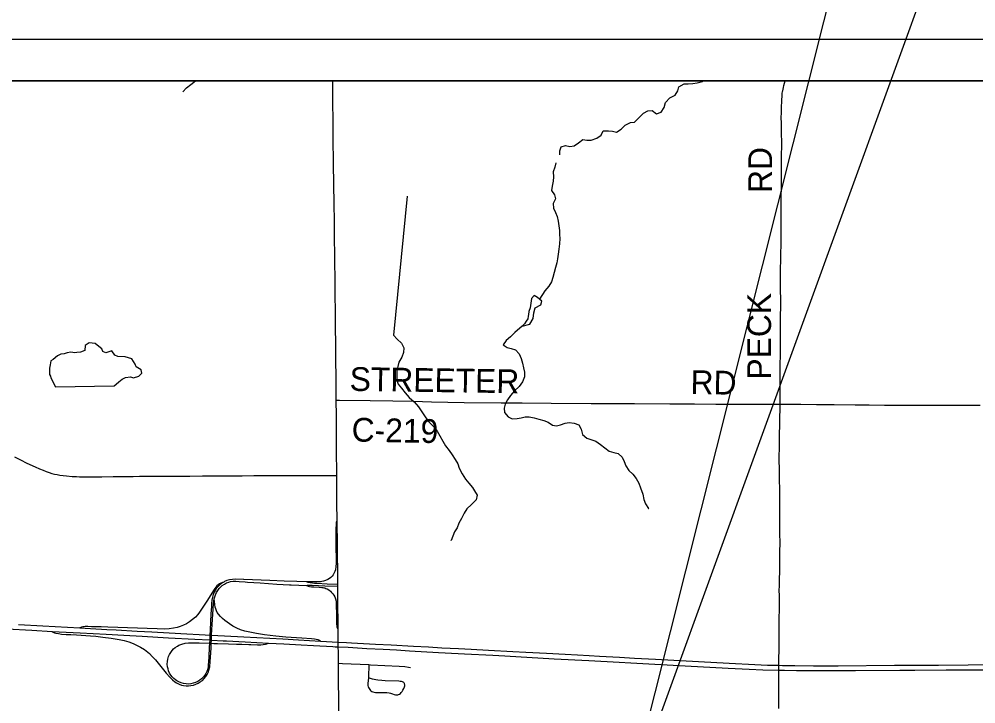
# Model space of a CAD drawing. Extents: x 0 to 34, y 0 to 22.
# Drawn here: x 25.975 to 28.262, y 18.436 to 20.071 of the extents above; entities that cross this region are included whole.
import ezdxf

# ---------------------------------------------------------------- set-up
doc = ezdxf.new("R2010")
doc.units = 0
for name, color, linetype in [('GM_X_Corporation', 7, 'Continuous'), ('GM_X_County_Road', 7, 'Continuous'), ('GM_X_County_Road_Text', 7, 'Continuous'), ('GM_X_Interchange_Ramps', 7, 'Continuous'), ('GM_X_Interstate_Route', 7, 'Continuous'), ('GM_X_Minor_Lake', 7, 'Continuous'), ('GM_X_Minor_River', 7, 'Continuous'), ('GM_X_State_Route', 7, 'Continuous'), ('GM_X_Township_Road', 7, 'Continuous'), ('SH_Data', 7, 'Continuous'), ('SH_Text', 7, 'Continuous')]:
    doc.layers.add(name, color=color, linetype=linetype)

msp = doc.modelspace()

# ---------------------------------------------------------------- linework, layer by layer
at = {"layer": 'GM_X_Corporation'}
msp.add_lwpolyline([(28.775, 16.6777), (28.7553, 18.174), (28.7532, 18.52), (28.7531, 18.5321), (28.758, 19.3951), (28.7506, 19.9239), (23.4438, 19.9239), (23.4438, 15.6034)], dxfattribs=at)
at = {"layer": 'GM_X_County_Road'}
for points in [[(27.7938, 19.1518), (27.7939, 19.1583), (27.794, 19.1918), (27.7944, 19.2353), (27.795, 19.2801), (27.7946, 19.3018), (27.7949, 19.3335), (27.7952, 19.3602), (27.7954, 19.3863), (27.7955, 19.4044), (27.7952, 19.4228), (27.7949, 19.4389), (27.7953, 19.4712), (27.7957, 19.4998), (27.796, 19.5171), (27.7963, 19.5271), (27.7963, 19.532), (27.7966, 19.549), (27.7966, 19.5841), (27.7966, 19.594), (27.7967, 19.6082), (27.7968, 19.6295), (27.7968, 19.6467), (27.7971, 19.6701), (27.7971, 19.6873), (27.7973, 19.7172), (27.7976, 19.7455), (27.7978, 19.7694), (27.7971, 19.8065), (27.7972, 19.8232), (27.7968, 19.8369), (27.797, 19.8473), (27.7973, 19.8597), (27.7981, 19.8773), (27.7987, 19.8887), (27.7991, 19.8939), (27.8, 19.8987), (27.8002, 19.9004), (27.802, 19.9082), (27.8031, 19.913), (27.806, 19.9239)], [(26.7331, 19.161), (26.7411, 19.1609), (26.8144, 19.1601), (26.8683, 19.1597), (26.9175, 19.159), (26.9608, 19.1573), (27.0385, 19.156), (27.1277, 19.1552), (27.1773, 19.1552), (27.2465, 19.1543), (27.3425, 19.1536), (27.3897, 19.1534), (27.4462, 19.1534), (27.5301, 19.1528), (27.5897, 19.1525), (27.6407, 19.152), (27.7333, 19.1516), (27.7938, 19.1518)], [(27.7907, 18.4249), (27.7908, 18.4405), (27.791, 18.4585), (27.7909, 18.4665), (27.7908, 18.4777), (27.7908, 18.4821), (27.791, 18.5094), (27.791, 18.5161), (27.7911, 18.5231), (27.7911, 18.5278), (27.7912, 18.5448), (27.7915, 18.5635), (27.7915, 18.5796), (27.7917, 18.5871), (27.792, 18.6057), (27.792, 18.6324), (27.7923, 18.6691), (27.7923, 18.6827), (27.7922, 18.69), (27.7922, 18.6919), (27.7923, 18.6961), (27.7921, 18.7047), (27.7923, 18.719), (27.7927, 18.7295), (27.7929, 18.7388), (27.793, 18.7462), (27.7931, 18.7491), (27.7932, 18.7633), (27.7933, 18.7801), (27.7937, 18.8), (27.7938, 18.8192), (27.7934, 18.8434), (27.793, 18.8837), (27.7932, 18.9057), (27.7931, 18.9325), (27.7924, 18.9867), (27.7921, 19.0273), (27.7925, 19.0463), (27.7929, 19.0737), (27.7933, 19.1079), (27.7938, 19.1518)], [(27.7938, 19.1518), (27.8017, 19.1517), (27.8434, 19.1514), (27.8808, 19.151), (27.9231, 19.1506), (27.9731, 19.1502), (28.0066, 19.1497), (28.0434, 19.1494), (28.0659, 19.1493), (28.1051, 19.1494), (28.1567, 19.1491), (28.1815, 19.1492), (28.2132, 19.1491), (28.2724, 19.149)]]:
    msp.add_lwpolyline(points, dxfattribs=at)
at = {"layer": 'GM_X_Interchange_Ramps'}
msp.add_line((26.6257, 18.7198), (26.6619, 18.7183), dxfattribs=at)
for points in [[(26.7351, 18.8718), (26.7345, 18.8715), (26.734, 18.871), (26.7333, 18.8696), (26.7331, 18.8684), (26.7328, 18.8634), (26.7324, 18.8556), (26.7321, 18.8308), (26.7324, 18.8119), (26.7326, 18.7804), (26.7327, 18.7706), (26.7325, 18.7644), (26.7323, 18.7616), (26.7317, 18.7581), (26.7311, 18.7555), (26.7298, 18.7516), (26.7276, 18.7471), (26.7258, 18.7441), (26.7235, 18.741), (26.7204, 18.7378), (26.7171, 18.7352), (26.7128, 18.7324), (26.7075, 18.73), (26.7028, 18.7284), (26.6991, 18.7278), (26.6957, 18.7275), (26.6893, 18.7275), (26.6834, 18.7275), (26.6754, 18.7273), (26.6692, 18.7272), (26.6623, 18.7269)], [(26.4648, 18.7268), (26.4616, 18.7256), (26.4577, 18.7242), (26.4541, 18.7226), (26.4509, 18.7202), (26.4478, 18.7174), (26.4451, 18.7143), (26.4411, 18.7087), (26.4238, 18.6814), (26.4158, 18.6688), (26.4065, 18.6549), (26.4024, 18.6495), (26.3966, 18.6431), (26.3896, 18.6369), (26.3826, 18.6317), (26.3752, 18.6272), (26.3679, 18.6237), (26.3598, 18.6205), (26.3527, 18.6183), (26.3442, 18.6164), (26.3338, 18.6151), (26.322, 18.6145), (26.3052, 18.6146), (26.1871, 18.6189), (26.1713, 18.6193), (26.1483, 18.6199), (26.1397, 18.6201), (26.1332, 18.6202), (26.1298, 18.62), (26.1277, 18.6196), (26.1247, 18.619), (26.1226, 18.6183), (26.1201, 18.6174)], [(26.4648, 18.7268), (26.46, 18.7237), (26.4549, 18.7198), (26.4506, 18.7158), (26.4472, 18.7117), (26.4443, 18.7076), (26.4416, 18.7025), (26.4392, 18.6972), (26.4373, 18.6908), (26.4361, 18.6835), (26.4353, 18.6752), (26.4348, 18.668), (26.4338, 18.6504), (26.4319, 18.6121), (26.4313, 18.6001), (26.4307, 18.5883), (26.4303, 18.5804), (26.4298, 18.5705), (26.4286, 18.5486), (26.4278, 18.5352), (26.4274, 18.5295), (26.4268, 18.5242), (26.4262, 18.5207), (26.4251, 18.5168), (26.4237, 18.5126), (26.4217, 18.5086), (26.4188, 18.504), (26.4159, 18.5002), (26.4114, 18.4955), (26.4069, 18.4922), (26.4022, 18.4891), (26.3971, 18.4866), (26.3916, 18.4848), (26.3855, 18.4834), (26.3794, 18.4829), (26.3741, 18.4832), (26.3678, 18.4842), (26.3624, 18.4857), (26.3572, 18.4879), (26.3525, 18.4906), (26.3486, 18.4931), (26.3448, 18.4964), (26.3409, 18.5004), (26.3377, 18.5044), (26.335, 18.5089), (26.3326, 18.5144), (26.3311, 18.5195), (26.3299, 18.5243), (26.3294, 18.5305), (26.3299, 18.5372), (26.3309, 18.5427), (26.3326, 18.5487), (26.3345, 18.5533), (26.3376, 18.5587), (26.3409, 18.5632), (26.3443, 18.5668), (26.3485, 18.5705), (26.3537, 18.5739), (26.357, 18.5756), (26.3639, 18.5785), (26.3717, 18.5804), (26.3798, 18.5814), (26.3891, 18.5817), (26.4058, 18.5812), (26.4299, 18.5804)], [(26.4416, 18.6865), (26.4447, 18.6963), (26.4471, 18.7019), (26.4498, 18.7067), (26.453, 18.7111), (26.4572, 18.7156), (26.4609, 18.7187), (26.466, 18.722), (26.471, 18.7245), (26.4766, 18.7265), (26.4808, 18.7276), (26.4868, 18.7285), (26.4934, 18.7286), (26.5015, 18.7279), (26.5154, 18.727)], [(26.5112, 18.7328), (26.4918, 18.7332), (26.485, 18.7328), (26.4778, 18.7316), (26.4719, 18.7302), (26.4664, 18.7277), (26.4648, 18.7268)], [(26.6623, 18.7269), (26.6389, 18.7278), (26.609, 18.7288), (26.5741, 18.7301), (26.5122, 18.7328), (26.5112, 18.7328)], [(26.5154, 18.727), (26.5213, 18.7266), (26.5515, 18.7247), (26.5911, 18.7219), (26.6216, 18.72), (26.6257, 18.7198)], [(26.737, 18.7211), (26.7112, 18.7218), (26.6871, 18.723), (26.6809, 18.7234), (26.6768, 18.7238), (26.671, 18.7247), (26.666, 18.7257), (26.6623, 18.7269)], [(26.6619, 18.7183), (26.6643, 18.7189), (26.667, 18.7192), (26.671, 18.7193), (26.6758, 18.7192), (26.7057, 18.718), (26.7371, 18.7168)], [(26.6619, 18.7183), (26.6657, 18.717), (26.6695, 18.7161), (26.674, 18.7156), (26.6796, 18.7153), (26.6927, 18.7144), (26.6985, 18.714), (26.7011, 18.7137), (26.7036, 18.7132), (26.7058, 18.7126), (26.7084, 18.7116), (26.7111, 18.7105), (26.7154, 18.708), (26.7193, 18.7049), (26.7222, 18.7021), (26.7254, 18.6983), (26.7276, 18.695), (26.7298, 18.691), (26.7315, 18.6868), (26.7326, 18.6814), (26.7331, 18.6764), (26.7333, 18.6705), (26.7334, 18.6503), (26.7335, 18.6428), (26.7338, 18.6282), (26.7345, 18.6191), (26.735, 18.6173), (26.7359, 18.6155), (26.7367, 18.6147), (26.7377, 18.6141)], [(26.0545, 18.6088), (26.0566, 18.6071), (26.0595, 18.6056), (26.0629, 18.6046), (26.0695, 18.6035), (26.0767, 18.6025), (26.0878, 18.6017), (26.0989, 18.601), (26.112, 18.6004), (26.1238, 18.5998), (26.1349, 18.5991), (26.1461, 18.5981), (26.1585, 18.5972), (26.1752, 18.5954), (26.1955, 18.5925), (26.2145, 18.5892), (26.226, 18.5867), (26.2374, 18.5836), (26.2479, 18.5797), (26.2575, 18.5753), (26.2657, 18.5708), (26.2746, 18.5652), (26.2826, 18.5592), (26.2868, 18.5556), (26.2935, 18.5491), (26.301, 18.5408), (26.327, 18.509), (26.3356, 18.4992), (26.3418, 18.4931), (26.3477, 18.4884), (26.3512, 18.486), (26.3579, 18.4825), (26.3637, 18.4804), (26.3679, 18.4794), (26.3741, 18.4787), (26.3797, 18.4786), (26.3859, 18.4792), (26.3919, 18.4805), (26.3979, 18.4825), (26.403, 18.4848), (26.4083, 18.488), (26.4132, 18.4918), (26.4176, 18.4961), (26.4216, 18.501), (26.4249, 18.5062), (26.4275, 18.5118), (26.429, 18.5159), (26.431, 18.5244), (26.4322, 18.5368), (26.4329, 18.5473), (26.4339, 18.5685), (26.4345, 18.5803), (26.4348, 18.5881), (26.4352, 18.5946), (26.4354, 18.5999), (26.4367, 18.625), (26.4387, 18.6622), (26.44, 18.6752), (26.4406, 18.6807), (26.4416, 18.6865)], [(26.6953, 18.5857), (26.6933, 18.5867), (26.6899, 18.5884), (26.6855, 18.5897), (26.6815, 18.5904), (26.6739, 18.5911), (26.651, 18.5927), (26.6126, 18.5951), (26.5884, 18.5972), (26.5749, 18.5987), (26.5619, 18.6005), (26.5423, 18.6037), (26.5265, 18.6067), (26.5144, 18.6097), (26.5044, 18.6129), (26.4952, 18.6168), (26.4864, 18.6214), (26.478, 18.6267), (26.4671, 18.6349), (26.4614, 18.6398), (26.4565, 18.6445), (26.452, 18.6496), (26.4489, 18.6542), (26.4467, 18.6582), (26.4451, 18.6627), (26.444, 18.6664), (26.4429, 18.6732), (26.4416, 18.6865)], [(26.431, 18.5804), (26.4345, 18.5803), (26.4409, 18.5801), (26.4495, 18.5798), (26.4756, 18.5789), (26.4944, 18.5783), (26.5078, 18.578), (26.5245, 18.5775), (26.5288, 18.5773), (26.5447, 18.5769), (26.5526, 18.5769), (26.5587, 18.5773), (26.5642, 18.578), (26.5673, 18.5791), (26.5713, 18.5808)]]:
    msp.add_lwpolyline(points, dxfattribs=at)
at = {"layer": 'GM_X_Interstate_Route'}
for points in [[(25.9456, 18.6153), (26.0053, 18.6114), (26.0545, 18.6088), (26.1213, 18.6055), (26.1835, 18.602), (26.2253, 18.5996), (26.2697, 18.5971), (26.3326, 18.5938), (26.3953, 18.5901), (26.4307, 18.5883), (26.4348, 18.5881), (26.4626, 18.5866)], [(25.9739, 18.6251), (26.0317, 18.6221), (26.1201, 18.6174)], [(26.1201, 18.6174), (26.1461, 18.6159), (26.185, 18.6137), (26.2069, 18.6125), (26.2576, 18.6097), (26.2924, 18.6079), (26.3618, 18.604), (26.4196, 18.6007), (26.4313, 18.6001), (26.4354, 18.5999), (26.5121, 18.5958), (26.6055, 18.5907), (26.6428, 18.5886), (26.6953, 18.5857), (26.738, 18.5833), (26.7577, 18.5822), (26.7694, 18.5816), (26.8273, 18.5785), (26.8646, 18.5766), (26.9181, 18.5736), (26.954, 18.5716), (26.9854, 18.5699), (27.0255, 18.5677), (27.0559, 18.566), (27.0968, 18.564), (27.1555, 18.5608), (27.1863, 18.5591), (27.2354, 18.5565), (27.2804, 18.5541), (27.31, 18.5526), (27.3379, 18.5509), (27.3626, 18.5495), (27.4104, 18.5469), (27.4457, 18.5451), (27.4962, 18.5422), (27.5991, 18.5366), (27.6719, 18.5328), (27.7332, 18.5298), (27.7639, 18.5285), (27.7837, 18.528), (27.7911, 18.5278), (27.8, 18.5277), (27.8291, 18.5271), (27.8736, 18.5267), (27.9327, 18.5268), (28.0677, 18.5278), (28.1722, 18.5285), (28.3143, 18.5295)], [(26.4626, 18.5866), (26.4705, 18.5862), (26.5152, 18.5838), (26.5713, 18.5808), (26.608, 18.5787), (26.649, 18.5764), (26.6792, 18.5749), (26.7247, 18.5725), (26.7309, 18.5722)], [(26.7309, 18.5722), (26.7381, 18.5719), (26.7616, 18.5708), (26.8064, 18.5683), (26.8454, 18.5662), (26.877, 18.5644), (26.9084, 18.5626), (26.9772, 18.5587), (26.9934, 18.5578), (27.04, 18.5553), (27.1075, 18.5517), (27.1361, 18.5502), (27.254, 18.5435), (27.3367, 18.5392), (27.4094, 18.5352), (27.437, 18.5337), (27.5674, 18.5267), (27.6701, 18.5211), (27.7199, 18.5184), (27.7528, 18.517), (27.791, 18.5161), (27.8044, 18.5158), (27.8331, 18.5155), (27.8682, 18.5151), (27.899, 18.5152), (27.9434, 18.5153), (27.9739, 18.5154), (28.0805, 18.516), (28.1156, 18.5162), (28.1907, 18.5169), (28.2201, 18.5172), (28.3081, 18.5173)]]:
    msp.add_lwpolyline(points, dxfattribs=at)
at = {"layer": 'GM_X_Minor_Lake'}
for p, q in [((27.1994, 19.3985), (27.1965, 19.3818)), ((26.051, 19.2144), (26.0621, 19.1928))]:
    msp.add_line(p, q, dxfattribs=at)
for points in [[(27.1965, 19.3818), (27.1935, 19.3734), (27.1928, 19.3658), (27.192, 19.362), (27.1909, 19.3555), (27.1871, 19.3502), (27.1834, 19.3433), (27.1779, 19.3382), (27.1959, 19.3426), (27.2038, 19.3567), (27.2053, 19.3697), (27.2086, 19.3818), (27.2219, 19.3888), (27.2249, 19.3979), (27.2142, 19.4062), (27.2062, 19.4111), (27.2002, 19.4039), (27.1994, 19.3985)], [(26.0621, 19.1928), (26.2026, 19.1951), (26.2075, 19.1996), (26.2139, 19.205), (26.2215, 19.2115), (26.2294, 19.2157), (26.2416, 19.2173), (26.2484, 19.2147), (26.2617, 19.2189), (26.2685, 19.2254), (26.2669, 19.2334), (26.2547, 19.2406), (26.2524, 19.2474), (26.2444, 19.2599), (26.2288, 19.2644), (26.2114, 19.2658), (26.2038, 19.2684), (26.1969, 19.279), (26.1821, 19.274), (26.1752, 19.2774), (26.1733, 19.2842), (26.1619, 19.2929), (26.1569, 19.2967), (26.1425, 19.2985), (26.1334, 19.292), (26.1327, 19.2802), (26.1221, 19.2756), (26.1134, 19.2752), (26.1085, 19.2744), (26.099, 19.2759), (26.0899, 19.2743), (26.0827, 19.272), (26.0751, 19.2712), (26.0671, 19.267), (26.0565, 19.2586), (26.0512, 19.2551), (26.0498, 19.246), (26.0479, 19.2376), (26.0476, 19.2289), (26.048, 19.2224), (26.0499, 19.2182), (26.051, 19.2144)]]:
    msp.add_lwpolyline(points, dxfattribs=at)
at = {"layer": 'GM_X_Minor_River'}
for points in [[(26.3667, 19.8976), (26.3754, 19.9071), (26.386, 19.9152), (26.3967, 19.9239)], [(27.2677, 19.7471), (27.2676, 19.7569), (27.2706, 19.7665), (27.2812, 19.7699), (27.2911, 19.7669), (27.3017, 19.7689), (27.3123, 19.7758), (27.3222, 19.7842), (27.3317, 19.7824), (27.3427, 19.782), (27.3559, 19.787), (27.3665, 19.7947), (27.3714, 19.8046), (27.3836, 19.805), (27.3934, 19.8036), (27.4029, 19.8017), (27.4139, 19.809), (27.4237, 19.8182), (27.4362, 19.8247), (27.4461, 19.8255), (27.4567, 19.8358), (27.4676, 19.8465), (27.4778, 19.8527), (27.4885, 19.8535), (27.4984, 19.8452), (27.5097, 19.849), (27.5169, 19.8601), (27.5203, 19.8726), (27.5308, 19.8837), (27.5433, 19.8899), (27.5497, 19.9005), (27.552, 19.9101), (27.5645, 19.9173), (27.574, 19.917), (27.585, 19.9174), (27.5956, 19.9194), (27.6085, 19.9229), (27.6101, 19.9239)], [(27.2583, 19.728), (27.2557, 19.7177), (27.2512, 19.7071), (27.2524, 19.6945), (27.2516, 19.6843), (27.2494, 19.6728), (27.2476, 19.6622), (27.2548, 19.6516), (27.2572, 19.6421), (27.2515, 19.6314), (27.2527, 19.6196), (27.2573, 19.6094), (27.2611, 19.5999), (27.2638, 19.5885), (27.265, 19.5775), (27.2666, 19.5665), (27.2667, 19.5566), (27.2675, 19.5471), (27.2668, 19.5346), (27.2653, 19.5216), (27.2634, 19.5098), (27.2616, 19.4992), (27.2601, 19.4893), (27.2575, 19.4779), (27.2542, 19.4661), (27.2508, 19.4539), (27.2474, 19.4436), (27.241, 19.4337), (27.2316, 19.4223), (27.219, 19.4024)], [(26.903, 19.6483), (26.87, 19.3167), (26.8788, 19.3068), (26.8891, 19.2974), (26.8944, 19.286), (26.8941, 19.275), (26.8903, 19.2643), (26.8824, 19.2521), (26.8806, 19.2418), (26.878, 19.2319), (26.878, 19.222), (26.8777, 19.2099), (26.8812, 19.1996), (26.8892, 19.1898), (26.8979, 19.1784), (26.9075, 19.1678), (26.9197, 19.1573), (26.93, 19.1451), (26.9453, 19.1217), (26.9544, 19.1092), (26.967, 19.0971), (26.9747, 19.0872), (26.9808, 19.0758), (26.988, 19.0633), (26.9945, 19.052), (27.0029, 19.0406), (27.0106, 19.0308), (27.0175, 19.0198), (27.0236, 19.0088), (27.0271, 18.9985), (27.0343, 18.9849), (27.0424, 18.9728), (27.0504, 18.9629), (27.0588, 18.9523), (27.0637, 18.9447)], [(27.1779, 19.3382), (27.1603, 19.3227), (27.1493, 19.3127), (27.1395, 19.3036), (27.132, 19.2933), (27.1419, 19.2872), (27.1514, 19.2846), (27.1616, 19.2816), (27.1704, 19.2718), (27.1754, 19.2608), (27.1785, 19.2498), (27.1808, 19.2388), (27.1828, 19.2285), (27.1828, 19.2167), (27.1787, 19.2053), (27.17, 19.1939), (27.1594, 19.1832), (27.15, 19.1725), (27.1424, 19.1622), (27.1368, 19.1515), (27.1346, 19.142), (27.1354, 19.1317), (27.1438, 19.1215), (27.154, 19.117), (27.1658, 19.1178), (27.1753, 19.1194), (27.1848, 19.1213), (27.1946, 19.121), (27.2064, 19.1188), (27.217, 19.1162), (27.2292, 19.1128), (27.2395, 19.1087), (27.2498, 19.1012), (27.2596, 19.1001), (27.2695, 19.1024), (27.2805, 19.1066), (27.29, 19.1078), (27.3017, 19.106), (27.3127, 19.1019), (27.3189, 19.0916), (27.3216, 19.0795), (27.3322, 19.0704), (27.3539, 19.0633), (27.365, 19.0554), (27.3752, 19.0474), (27.3855, 19.0391), (27.3969, 19.0365), (27.4068, 19.0339), (27.4163, 19.0248), (27.4213, 19.0146), (27.4255, 19.0044), (27.4324, 18.993), (27.4423, 18.9847), (27.4503, 18.9737), (27.4565, 18.9631), (27.4603, 18.9517)], [(27.0637, 18.9447), (27.0701, 18.9344), (27.0676, 18.923), (27.0564, 18.9122), (27.0455, 18.9014), (27.0392, 18.8911), (27.0329, 18.8789), (27.0258, 18.867), (27.0218, 18.8563), (27.0158, 18.8464), (27.0121, 18.8361), (27.0077, 18.8262), (27.0081, 18.8269)], [(27.4603, 18.9517), (27.4659, 18.9363), (27.4679, 18.9242), (27.4722, 18.9132), (27.4795, 18.9027), (27.4799, 18.9027)]]:
    msp.add_lwpolyline(points, dxfattribs=at)
at = {"layer": 'GM_X_State_Route'}
for points in [[(26.7351, 18.8789), (26.7347, 18.9112), (26.7342, 18.9815), (26.7338, 19.0452), (26.7334, 19.1235), (26.7331, 19.161), (26.7328, 19.1912), (26.7322, 19.2814), (26.7314, 19.3491), (26.7306, 19.4371), (26.7298, 19.5054), (26.7292, 19.5513), (26.7287, 19.5894), (26.7282, 19.6295), (26.727, 19.7258), (26.7262, 19.7883), (26.7261, 19.805), (26.726, 19.8236), (26.7254, 19.8783), (26.7253, 19.9069), (26.725, 19.9239)], [(26.7382, 18.5588), (26.7381, 18.5719), (26.738, 18.5833), (26.7377, 18.6141), (26.7377, 18.6194), (26.7373, 18.6834), (26.7371, 18.7168), (26.737, 18.7211), (26.737, 18.7294), (26.7358, 18.8148), (26.7351, 18.8718), (26.7351, 18.8789)], [(26.7425, 18.1697), (26.7409, 18.2627), (26.7404, 18.3254), (26.7398, 18.3845), (26.7389, 18.4957), (26.7384, 18.5326), (26.7382, 18.5588)]]:
    msp.add_lwpolyline(points, dxfattribs=at)
at = {"layer": 'GM_X_Township_Road'}
for points in [[(25.964, 19.0257), (25.9786, 19.0184), (25.9937, 19.011), (26.0135, 19.0019), (26.0239, 18.9973), (26.0324, 18.9936), (26.0399, 18.9908), (26.0471, 18.9884), (26.0536, 18.9864), (26.06, 18.9848), (26.0665, 18.9834), (26.0725, 18.9823), (26.0806, 18.9811), (26.0882, 18.9803), (26.1024, 18.9791), (26.1123, 18.9786), (26.1198, 18.9783), (26.129, 18.978), (26.141, 18.9779), (26.1726, 18.9782), (26.2, 18.9785), (26.222, 18.9788), (26.2478, 18.9791), (26.2631, 18.9793), (26.2824, 18.9795), (26.3076, 18.9797), (26.3369, 18.9798), (26.3834, 18.98), (26.4138, 18.9801), (26.4448, 18.9802), (26.4768, 18.9805), (26.5081, 18.9807), (26.5361, 18.9809), (26.5624, 18.9811), (26.582, 18.9812), (26.609, 18.9813), (26.6406, 18.9815), (26.6695, 18.9816), (26.696, 18.9816), (26.7342, 18.9815)], [(26.7384, 18.5326), (26.7485, 18.5321), (26.8108, 18.5294), (26.815, 18.5292), (26.8832, 18.5256), (26.8968, 18.5247), (26.9061, 18.5236), (26.911, 18.5228)], [(26.8108, 18.5294), (26.8107, 18.5237), (26.8102, 18.5057), (26.8103, 18.4976), (26.8088, 18.4842), (26.809, 18.4792), (26.8094, 18.4767), (26.8102, 18.4744), (26.8115, 18.4723), (26.8149, 18.4679), (26.8162, 18.4666), (26.8183, 18.4652), (26.8206, 18.4643), (26.8236, 18.4635), (26.8273, 18.463), (26.8329, 18.4629), (26.8472, 18.4629), (26.8541, 18.4626), (26.8596, 18.4621), (26.8627, 18.4615), (26.8678, 18.4594), (26.8719, 18.4578), (26.8749, 18.4571), (26.878, 18.457), (26.8805, 18.4575), (26.8822, 18.458), (26.8844, 18.4592), (26.8865, 18.4606), (26.8887, 18.4628), (26.8907, 18.4652), (26.8927, 18.4683), (26.8947, 18.4722), (26.8963, 18.4763), (26.8969, 18.4787), (26.8971, 18.4805), (26.8961, 18.4845), (26.8958, 18.485), (26.8946, 18.4865), (26.8932, 18.4876), (26.8915, 18.4884), (26.8891, 18.489), (26.886, 18.4893), (26.8829, 18.4895), (26.8498, 18.4908), (26.8423, 18.4912), (26.8328, 18.4921), (26.8276, 18.4928), (26.8195, 18.495), (26.8103, 18.4976)]]:
    msp.add_lwpolyline(points, dxfattribs=at)
at = {"layer": 'SH_Data'}
for p, q in [((23.3438, 20.0239), (30.3438, 20.0239)), ((23.4438, 19.9239), (30.2438, 19.9239))]:
    msp.add_line(p, q, dxfattribs=at)
at = {"layer": 'SH_Text'}
msp.add_lwpolyline([(27.9346, 20.2119), (27.4216, 18.1707), (28.1627, 20.2119), (27.9346, 20.2119)], dxfattribs=at)

# ---------------------------------------------------------------- texts
at = {"layer": 'GM_X_County_Road_Text'}
for s, rotation, p in [('RD', 90, (27.7748, 19.6562)), ('PECK', 90, (27.7723, 19.2104)), ('STREETER', 359.1747, (26.765, 19.1835)), ('RD', 359.0186, (27.5795, 19.176)), ('C-219', 358.9205, (26.7696, 19.0625))]:
    msp.add_text(s, height=0.05682, rotation=rotation, dxfattribs=at).set_placement(p)

doc.saveas('drawing.dxf')
